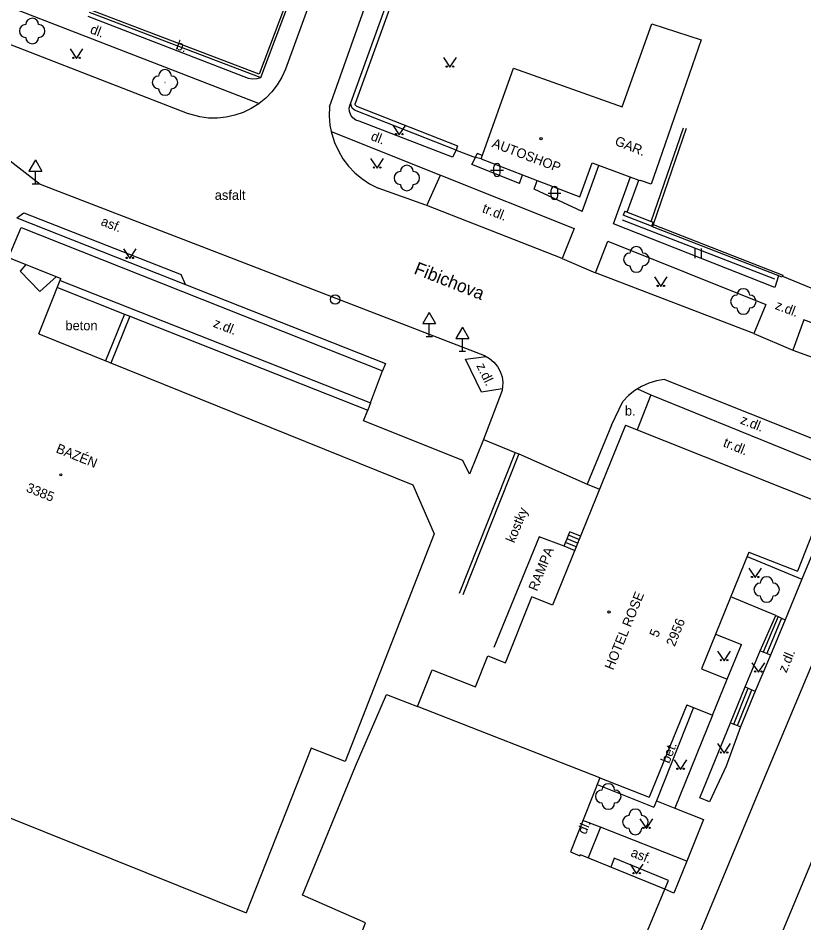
# Model space of a CAD drawing. Extents: x -584400 to -581602, y -1210894 to -1208793.
# Drawn here: x -583343.1 to -583281.7, y -1210558.7 to -1210488 of the extents above; entities that cross this region are included whole.
import ezdxf

# ---------------------------------------------------------------- set-up
doc = ezdxf.new("R2010")
doc.units = 0
for name, color, linetype in [('BUDOVY_MĚŘ', 7, 'Continuous'), ('MAP_ZN_BP', 7, 'Continuous'), ('NÁZVY_ULIC_TOK_SMĚR', 7, 'Continuous'), ('POMOC_POPIS', 7, 'Continuous'), ('ROZHRANÍ_PLOCH', 7, 'Continuous'), ('ZELEŇ', 7, 'Continuous'), ('ZN_BUDOV', 7, 'Continuous'), ('ZN_DOPLŇKOVÉ', 7, 'Continuous'), ('ZN_KULTUR', 7, 'Continuous'), ('Č_POPIS_EVID', 7, 'Continuous')]:
    doc.layers.add(name, color=color, linetype=linetype)

msp = doc.modelspace()

# ---------------------------------------------------------------- linework, layer by layer
at = {"layer": 'BUDOVY_MĚŘ'}
for points in [[(-583306.95, -1210499.01), (-583304.42, -1210491.92), (-583295.92, -1210494.95), (-583293.6, -1210488.45), (-583289.76, -1210489.69), (-583293.04, -1210499.19), (-583293.66, -1210500.99), (-583294.49, -1210500.7)], [(-583306.95, -1210499.01), (-583303.72, -1210500.26)], [(-583302.56, -1210500.7), (-583299.23, -1210501.98), (-583298.26, -1210499.32), (-583294.61, -1210500.66), (-583294.49, -1210500.7)], [(-583358.67, -1210504.38), (-583355.01, -1210502.25), (-583339.78, -1210508.36)], [(-583341.52, -1210512.69), (-583339.78, -1210508.36)], [(-583341.52, -1210512.69), (-583312.28, -1210524.49), (-583310.62, -1210528.33)], [(-583295.67, -1210519.82), (-583301.37, -1210533.9), (-583302.98, -1210533.25)], [(-583295.67, -1210519.82), (-583280.16, -1210526), (-583282.23, -1210531.25)], [(-583310.62, -1210528.33), (-583317.56, -1210546.13), (-583320.24, -1210545.08), (-583325.3, -1210557.96)], [(-583286.02, -1210529.75), (-583289.73, -1210538.88), (-583287.71, -1210539.7)], [(-583286.02, -1210529.75), (-583282.23, -1210531.25)], [(-583311.91, -1210541.83), (-583310.78, -1210538.95), (-583307.38, -1210540.28), (-583306.43, -1210537.86), (-583305.05, -1210538.4), (-583302.98, -1210533.25)], [(-583372.65, -1210538.93), (-583325.3, -1210557.96)], [(-583290.88, -1210541.69), (-583288.85, -1210542.51), (-583287.71, -1210539.7)], [(-583307.97, -1210568.9), (-583318.27, -1210564.75), (-583315.99, -1210558.73), (-583320.9, -1210556.58), (-583316.75, -1210546.49), (-583314.35, -1210540.88), (-583311.91, -1210541.83)], [(-583297.66, -1210547.41), (-583311.91, -1210541.83)], [(-583290.88, -1210541.69), (-583293.82, -1210548.92)], [(-583297.66, -1210547.41), (-583299.97, -1210553.19), (-583299.22, -1210553.49), (-583299.19, -1210553.42)], [(-583297.66, -1210547.41), (-583293.82, -1210548.92)], [(-583294.2, -1210559.98), (-583292.59, -1210556.1), (-583299.19, -1210553.42)]]:
    msp.add_lwpolyline(points, dxfattribs=at)
at = {"layer": 'MAP_ZN_BP'}
for radius in [0.375, 0.0005]:
    msp.add_circle((-583318.35, -1210510.001), radius, dxfattribs=at)
at = {"layer": 'ROZHRANÍ_PLOCH'}
for points in [[(-583313.01, -1210330.05), (-583293.77, -1210336.88), (-583274.64, -1210343.78), (-583274.01, -1210344.01), (-583273.4, -1210344.32), (-583272.84, -1210344.7), (-583272.32, -1210345.14), (-583271.87, -1210345.64), (-583271.47, -1210346.19), (-583271.14, -1210346.78), (-583270.88, -1210347.41), (-583270.7, -1210348.06), (-583270.59, -1210348.73), (-583270.57, -1210349.41), (-583270.62, -1210350.09), (-583270.76, -1210350.75), (-583270.94, -1210351.31), (-583322.23, -1210492)], [(-583318.8, -1210494.94), (-583312.35, -1210476.76)], [(-583356.54, -1210482.16), (-583324.28, -1210494.67)], [(-583324.28, -1210494.67), (-583324.32, -1210494.7), (-583324.91, -1210495.07), (-583325.53, -1210495.37), (-583326.18, -1210495.6), (-583326.86, -1210495.75), (-583327.55, -1210495.82), (-583328.24, -1210495.82), (-583328.93, -1210495.73), (-583329.9, -1210495.46), (-583348.95, -1210488.05)], [(-583337.69, -1210487.86), (-583325.15, -1210492.7), (-583324.8, -1210492.75), (-583324.44, -1210492.72), (-583324.16, -1210492.64)], [(-583322.23, -1210492), (-583322.52, -1210492.63), (-583322.88, -1210493.22), (-583323.3, -1210493.77), (-583323.78, -1210494.27), (-583324.28, -1210494.67)], [(-583350.67, -1210493.78), (-583341.4, -1210500.99), (-583306.67, -1210514.38), (-583306.29, -1210514.61), (-583305.95, -1210514.9), (-583305.67, -1210515.24), (-583305.46, -1210515.64), (-583305.31, -1210516.06), (-583305.25, -1210516.5), (-583305.3, -1210517.12), (-583306.75, -1210520.95)], [(-583318.8, -1210494.94), (-583318.82, -1210495.65), (-583318.76, -1210496.36), (-583318.66, -1210496.87)], [(-583308.9, -1210498.32), (-583309.17, -1210498.87), (-583316.48, -1210496.07), (-583316.74, -1210495.97), (-583316.97, -1210495.8), (-583317.14, -1210495.58), (-583317.23, -1210495.31), (-583317.25, -1210495.03), (-583317.19, -1210494.76), (-583317.13, -1210494.62)], [(-583318.66, -1210496.87), (-583318.61, -1210497.06), (-583318.4, -1210497.74), (-583318.1, -1210498.39), (-583317.74, -1210499.01), (-583317.31, -1210499.57), (-583316.81, -1210500.09), (-583316.27, -1210500.55), (-583315.67, -1210500.95), (-583315, -1210501.29)], [(-583318.66, -1210496.87), (-583310.13, -1210500.29)], [(-583307.67, -1210499.46), (-583307.38, -1210498.91)], [(-583303.94, -1210500.92), (-583307.67, -1210499.46)], [(-583299.04, -1210503.11), (-583297.74, -1210499.52)], [(-583310.13, -1210500.29), (-583299.68, -1210504.46), (-583300.6, -1210506.8), (-583311.18, -1210502.66), (-583310.13, -1210500.29)], [(-583303.94, -1210500.92), (-583303.72, -1210500.26)], [(-583302.79, -1210501.37), (-583302.56, -1210500.7)], [(-583283.7, -1210508.15), (-583283.99, -1210509.07), (-583296.6, -1210504.08), (-583295.27, -1210500.42)], [(-583311.26, -1210502.63), (-583315, -1210501.29)], [(-583299.04, -1210503.11), (-583302.79, -1210501.37)], [(-583343.23, -1210503.61), (-583342.67, -1210503.22), (-583330.38, -1210508.06)], [(-583343.23, -1210503.61), (-583330.05, -1210508.83)], [(-583343.87, -1210506.72), (-583342.9, -1210504.38), (-583314.65, -1210515.58)], [(-583298.01, -1210507.91), (-583297.05, -1210505.45), (-583284.69, -1210510.4), (-583285.63, -1210512.65), (-583298.01, -1210507.91)], [(-583342.52, -1210507.26), (-583342.96, -1210507.78), (-583341.44, -1210509.39), (-583340.13, -1210508.21)], [(-583300.6, -1210506.8), (-583298.01, -1210507.91)], [(-583339.84, -1210508.51), (-583315.6, -1210518.09), (-583315.81, -1210518.65)], [(-583330.05, -1210508.83), (-583330.38, -1210508.06)], [(-583340.06, -1210509.07), (-583334.81, -1210511.14)], [(-583330.05, -1210508.83), (-583314.43, -1210515.02), (-583314.65, -1210515.58)], [(-583334.81, -1210511.14), (-583336.3, -1210514.8)], [(-583334.39, -1210511.31), (-583335.89, -1210514.97)], [(-583334.81, -1210511.14), (-583334.39, -1210511.31)], [(-583334.39, -1210511.31), (-583315.81, -1210518.65)], [(-583272.19, -1210517.74), (-583271.46, -1210515.49), (-583281.72, -1210511.59), (-583282.59, -1210513.96), (-583272.19, -1210517.74)], [(-583285.63, -1210512.65), (-583282.59, -1210513.96)], [(-583305.29, -1210517), (-583306.91, -1210517.26), (-583308.17, -1210514.66), (-583306.54, -1210514.46)], [(-583315.6, -1210518.09), (-583314.65, -1210515.58)], [(-583292.64, -1210516.25), (-583293.25, -1210516.36), (-583293.85, -1210516.54), (-583294.41, -1210516.8), (-583294.94, -1210517.12), (-583295.43, -1210517.52), (-583295.87, -1210517.99)], [(-583271.92, -1210529.55), (-583272.06, -1210528.73), (-583272.28, -1210527.92), (-583272.58, -1210527.13), (-583272.94, -1210526.38), (-583273.37, -1210525.69), (-583274.55, -1210524.17), (-583275.05, -1210523.69), (-583275.59, -1210523.27), (-583276.18, -1210522.91), (-583276.81, -1210522.63), (-583276.98, -1210522.57), (-583279.19, -1210521.64), (-583292.64, -1210516.25)], [(-583294.73, -1210516.98), (-583293.67, -1210517.46), (-583294.74, -1210520.19)], [(-583293.67, -1210517.46), (-583279.82, -1210523.09)], [(-583296.76, -1210519.82), (-583295.87, -1210517.99)], [(-583306.75, -1210520.95), (-583307.86, -1210523.67), (-583308.38, -1210522.59), (-583316.14, -1210519.48), (-583315.81, -1210518.65)], [(-583296.76, -1210519.82), (-583298.65, -1210524.45)], [(-583306.75, -1210520.95), (-583304.28, -1210521.97)], [(-583304, -1210522.08), (-583298.65, -1210524.45)], [(-583280.88, -1210525.72), (-583279.82, -1210523.09), (-583278.92, -1210524.73), (-583281.87, -1210531.86)], [(-583298.65, -1210524.45), (-583297.7, -1210524.83)], [(-583300.23, -1210528.72), (-583300.12, -1210528.44)], [(-583300.12, -1210528.44), (-583300.01, -1210528.17)], [(-583299.3, -1210528.78), (-583300.12, -1210528.44)], [(-583299.18, -1210528.5), (-583300.01, -1210528.17)], [(-583300.46, -1210529.29), (-583302.4, -1210528.55), (-583305.94, -1210537.22)], [(-583300.46, -1210529.29), (-583300.34, -1210529)], [(-583300.34, -1210529), (-583300.23, -1210528.72)], [(-583299.52, -1210529.34), (-583300.34, -1210529)], [(-583299.41, -1210529.06), (-583300.23, -1210528.72)], [(-583299.64, -1210529.63), (-583300.46, -1210529.29)], [(-583286.16, -1210530.11), (-583281.87, -1210531.86)], [(-583281.87, -1210531.86), (-583283.19, -1210535.05)], [(-583283.91, -1210534.71), (-583287.44, -1210533.25)], [(-583285.13, -1210537.48), (-583283.91, -1210534.71)], [(-583283.74, -1210534.79), (-583284.9, -1210537.57)], [(-583283.91, -1210534.71), (-583283.74, -1210534.79)], [(-583283.74, -1210534.79), (-583283.47, -1210534.92)], [(-583283.47, -1210534.92), (-583284.62, -1210537.69)], [(-583283.19, -1210535.05), (-583284.34, -1210537.8)], [(-583283.47, -1210534.92), (-583283.19, -1210535.05)], [(-583288.63, -1210536.17), (-583286.6, -1210536.99)], [(-583287.71, -1210539.7), (-583286.6, -1210536.99)], [(-583294.34, -1210570.37), (-583284.9, -1210547.66), (-583280.49, -1210537.15)], [(-583286.32, -1210540.3), (-583285.13, -1210537.48)], [(-583284.9, -1210537.57), (-583285.13, -1210537.48)], [(-583284.62, -1210537.69), (-583284.9, -1210537.57)], [(-583284.34, -1210537.8), (-583284.62, -1210537.69)], [(-583284.34, -1210537.8), (-583285.52, -1210540.63)], [(-583311.81, -1210627.97), (-583302.23, -1210604.91), (-583291.71, -1210579.41), (-583279.57, -1210550.25), (-583275.08, -1210539.62)], [(-583287.46, -1210543.1), (-583286.32, -1210540.3)], [(-583287.2, -1210543.2), (-583286.07, -1210540.4)], [(-583286.92, -1210543.31), (-583285.8, -1210540.51)], [(-583286.32, -1210540.3), (-583286.07, -1210540.4)], [(-583286.07, -1210540.4), (-583285.8, -1210540.51)], [(-583285.8, -1210540.51), (-583285.52, -1210540.63)], [(-583285.52, -1210540.63), (-583286.68, -1210543.41)], [(-583290.34, -1210541.91), (-583293.25, -1210549.21)], [(-583288.85, -1210542.51), (-583291.81, -1210549.77)], [(-583286.68, -1210543.41), (-583287.8, -1210546.5), (-583289.09, -1210549.28), (-583289.84, -1210548.96), (-583287.46, -1210543.1)], [(-583287.46, -1210543.1), (-583287.2, -1210543.2)], [(-583287.2, -1210543.2), (-583286.92, -1210543.31)], [(-583286.92, -1210543.31), (-583286.68, -1210543.41)], [(-583297.87, -1210547.93), (-583293.45, -1210549.7)], [(-583293.25, -1210549.21), (-583293.45, -1210549.7)], [(-583293.25, -1210549.21), (-583291.81, -1210549.77)], [(-583291.81, -1210549.77), (-583289.57, -1210550.65), (-583290.87, -1210553.92)], [(-583297.61, -1210551.27), (-583298.99, -1210550.73)], [(-583297.61, -1210551.27), (-583298.58, -1210553.67)], [(-583290.87, -1210553.92), (-583297.61, -1210551.27)], [(-583290.87, -1210553.92), (-583291.89, -1210556.43), (-583292.59, -1210556.1), (-583292.31, -1210555.44), (-583296.54, -1210553.69), (-583296.81, -1210554.39)], [(-583290.85, -1210553.93), (-583290.87, -1210553.92)]]:
    msp.add_lwpolyline(points, dxfattribs=at)
at = {"layer": 'ZELEŇ'}
for centre in [(-583342.03, -1210489.01), (-583331.65, -1210493.03), (-583312.75, -1210500.5), (-583294.81, -1210506.87), (-583286.45, -1210510.16), (-583284.63, -1210532.68), (-583297.01, -1210548.86), (-583294.89, -1210550.85)]:
    msp.add_circle(centre, 0.0005, dxfattribs=at)
for centre, start, end in [((-583342.03, -1210488.51), 0, 179.99999), ((-583342.53, -1210489.01), 89.99999, 269.99999), ((-583341.53, -1210489.01), 270, 89.99999), ((-583342.03, -1210489.51), 179.99999, 359.99999), ((-583331.65, -1210492.53), 0, 179.99999), ((-583332.15, -1210493.03), 89.99999, 269.99999), ((-583331.15, -1210493.03), 270, 89.99999), ((-583331.65, -1210493.53), 179.99999, 359.99999), ((-583312.75, -1210500), 0, 179.99999), ((-583313.25, -1210500.5), 89.99999, 269.99999), ((-583312.25, -1210500.5), 270, 89.99999), ((-583312.75, -1210501), 179.99999, 359.99999), ((-583294.81, -1210506.37), 0, 179.99999), ((-583295.31, -1210506.87), 89.99999, 269.99999), ((-583294.31, -1210506.87), 270, 89.99999), ((-583294.81, -1210507.37), 179.99999, 359.99999), ((-583286.45, -1210509.66), 0, 179.99999), ((-583286.95, -1210510.16), 89.99999, 269.99999), ((-583285.95, -1210510.16), 270, 89.99999), ((-583286.45, -1210510.66), 179.99999, 359.99999), ((-583284.63, -1210532.18), 0, 179.99999), ((-583285.13, -1210532.68), 89.99999, 269.99999), ((-583284.13, -1210532.68), 270, 89.99999), ((-583284.63, -1210533.18), 179.99999, 359.99999), ((-583297.01, -1210548.36), 0, 179.99999), ((-583297.51, -1210548.86), 89.99999, 269.99999), ((-583296.51, -1210548.86), 270, 89.99999), ((-583297.01, -1210549.36), 179.99999, 359.99999), ((-583295.39, -1210550.85), 89.99999, 269.99999), ((-583294.89, -1210550.35), 0, 179.99999), ((-583294.39, -1210550.85), 270, 89.99999), ((-583294.89, -1210551.35), 179.99999, 359.99999)]:
    msp.add_arc(centre, 0.5, start, end, dxfattribs=at)
at = {"layer": 'ZN_BUDOV'}
for centre in [(-583302.26, -1210497.42), (-583339.79, -1210523.71), (-583296.95, -1210534.43)]:
    msp.add_circle(centre, 0.0875, dxfattribs=at)
at = {"layer": 'ZN_DOPLŇKOVÉ'}
for p, q in [((-583341.78, -1210499.094), (-583342.28, -1210499.96)), ((-583341.78, -1210499.094), (-583341.28, -1210499.96)), ((-583342.28, -1210499.96), (-583341.28, -1210499.96)), ((-583341.78, -1210500.96), (-583341.78, -1210499.96)), ((-583342.03, -1210500.96), (-583341.53, -1210500.96)), ((-583311, -1210511.024), (-583311.5, -1210511.89)), ((-583311, -1210511.024), (-583310.5, -1210511.89)), ((-583311.5, -1210511.89), (-583310.5, -1210511.89)), ((-583311, -1210512.89), (-583311, -1210511.89)), ((-583308.41, -1210512.174), (-583308.91, -1210513.04)), ((-583308.41, -1210512.174), (-583307.91, -1210513.04)), ((-583311.25, -1210512.89), (-583310.75, -1210512.89)), ((-583308.91, -1210513.04), (-583307.91, -1210513.04)), ((-583308.41, -1210514.04), (-583308.41, -1210513.04)), ((-583308.66, -1210514.04), (-583308.16, -1210514.04))]:
    msp.add_line(p, q, dxfattribs=at)
for points in [[(-583308.78, -1210498), (-583308.9, -1210498.32), (-583316.85, -1210495.19), (-583317.01, -1210495.04), (-583317.11, -1210494.84), (-583317.13, -1210494.62), (-583310.92, -1210477.46), (-583310.56, -1210477.47)], [(-583310.56, -1210477.47), (-583316.79, -1210494.69)], [(-583337.57, -1210487.53), (-583324.16, -1210492.64), (-583318.68, -1210478.09)], [(-583318.86, -1210478.02), (-583324.28, -1210492.38), (-583337.5, -1210487.35)], [(-583316.69, -1210494.88), (-583316.78, -1210494.77), (-583316.79, -1210494.69)], [(-583316.69, -1210494.88), (-583308.78, -1210498)], [(-583293.65, -1210503.91), (-583291.13, -1210496.57)], [(-583290.92, -1210496.64), (-583293.5, -1210504.14)], [(-583308.9, -1210498.32), (-583307.38, -1210498.91)], [(-583307.38, -1210498.91), (-583307.26, -1210498.59)], [(-583306.85, -1210498.75), (-583307.26, -1210498.59)], [(-583306.95, -1210499.01), (-583307.38, -1210498.91)], [(-583303.72, -1210500.26), (-583302.56, -1210500.7)], [(-583295.53, -1210503.17), (-583294.61, -1210500.66)], [(-583295.72, -1210503.1), (-583295.84, -1210503.41)], [(-583293.64, -1210504.28), (-583295.84, -1210503.41)], [(-583295.72, -1210503.1), (-583293.65, -1210503.91)], [(-583283.98, -1210508.41), (-583295.9, -1210503.8)], [(-583293.65, -1210503.91), (-583293.51, -1210503.96)], [(-583293.51, -1210503.96), (-583293.64, -1210504.28)], [(-583293.56, -1210504.31), (-583293.64, -1210504.28)], [(-583293.5, -1210504.14), (-583293.56, -1210504.31)], [(-583283.36, -1210508.09), (-583283.42, -1210508.26), (-583293.56, -1210504.31)], [(-583293.5, -1210504.14), (-583283.36, -1210508.09)], [(-583283.39, -1210508.17), (-583281.18, -1210509.09)], [(-583304.28, -1210521.97), (-583308.66, -1210532.98)], [(-583304.28, -1210521.97), (-583304, -1210522.08), (-583308.38, -1210533.09)]]:
    msp.add_lwpolyline(points, dxfattribs=at)
at = {"layer": 'ZN_KULTUR'}
for p, q in [((-583306.2, -1210499.88), (-583305.2, -1210499.88)), ((-583305.95, -1210500.13), (-583305.95, -1210499.63)), ((-583305.45, -1210500.13), (-583305.45, -1210499.63)), ((-583301.46, -1210501.93), (-583301.46, -1210501.43)), ((-583300.96, -1210501.93), (-583300.96, -1210501.43)), ((-583301.71, -1210501.68), (-583300.71, -1210501.68)), ((-583290.21, -1210506.765), (-583290.21, -1210506.015)), ((-583289.71, -1210506.765), (-583289.71, -1210506.015))]:
    msp.add_line(p, q, dxfattribs=at)
for points in [[(-583339.06, -1210490.41), (-583338.56, -1210491.16), (-583338.06, -1210490.41)], [(-583309.88, -1210491.09), (-583309.38, -1210491.84), (-583308.88, -1210491.09)], [(-583313.84, -1210496.37), (-583313.34, -1210497.12), (-583312.84, -1210496.37)], [(-583315.58, -1210498.98), (-583315.08, -1210499.73), (-583314.58, -1210498.98)], [(-583334.9, -1210506.05), (-583334.4, -1210506.8), (-583333.9, -1210506.05)], [(-583293.4, -1210508.24), (-583292.9, -1210508.99), (-583292.4, -1210508.24)], [(-583286.03, -1210531), (-583285.53, -1210531.75), (-583285.03, -1210531)], [(-583288.46, -1210537.5), (-583287.96, -1210538.25), (-583287.46, -1210537.5)], [(-583285.78, -1210538.4), (-583285.28, -1210539.15), (-583284.78, -1210538.4)], [(-583288.46, -1210544.72), (-583287.96, -1210545.47), (-583287.46, -1210544.72)], [(-583291.86, -1210545.99), (-583291.36, -1210546.74), (-583290.86, -1210545.99)], [(-583294.53, -1210550.61), (-583294.03, -1210551.36), (-583293.53, -1210550.61)], [(-583295.29, -1210554.15), (-583294.79, -1210554.9), (-583294.29, -1210554.15)]]:
    msp.add_lwpolyline(points, dxfattribs=at)
for centre in [(-583338.81, -1210491.11), (-583338.31, -1210491.11), (-583309.63, -1210491.79), (-583309.13, -1210491.79), (-583313.59, -1210497.07), (-583313.09, -1210497.07), (-583315.33, -1210499.68), (-583314.83, -1210499.68), (-583334.65, -1210506.75), (-583334.15, -1210506.75), (-583293.15, -1210508.94), (-583292.65, -1210508.94), (-583285.78, -1210531.7), (-583285.28, -1210531.7), (-583288.21, -1210538.2), (-583287.71, -1210538.2), (-583285.53, -1210539.1), (-583285.03, -1210539.1), (-583288.21, -1210545.42), (-583287.71, -1210545.42), (-583291.61, -1210546.69), (-583291.11, -1210546.69), (-583294.28, -1210551.31), (-583293.78, -1210551.31), (-583295.04, -1210554.85), (-583294.54, -1210554.85)]:
    msp.add_circle(centre, 0.05, dxfattribs=at)
for centre, start, end in [((-583305.7, -1210499.63), 0, 179.99999), ((-583305.7, -1210500.13), 179.99999, 359.99999), ((-583301.21, -1210501.43), 0, 179.99999), ((-583301.21, -1210501.93), 179.99999, 359.99999)]:
    msp.add_arc(centre, 0.25, start, end, dxfattribs=at)

# ---------------------------------------------------------------- texts
at = {"layer": 'NÁZVY_ULIC_TOK_SMĚR'}
msp.add_text('Fibichova', height=1, rotation=338.457, dxfattribs=at).set_placement((-583312.26, -1210507.96))
at = {"layer": 'POMOC_POPIS'}
for s, rotation, p in [('dl.', 338.80438, (-583337.56, -1210489.16)), ('b.', 338.89514, (-583330.86, -1210490.4)), ('dl.', 338.96246, (-583315.62, -1210497.52)), ('GAR.', 338.11299, (-583296.56, -1210497.89)), ('AUTOSHOP', 339.22774, (-583306.16, -1210498.07)), ('tr.dl.', 338.62361, (-583306.92, -1210503.16)), ('asf.', 338.50553, (-583336.72, -1210504.17)), ('z.dl.', 339.18735, (-583284.03, -1210510.73)), ('z.dl.', 338.43534, (-583327.94, -1210512.12)), ('z.dl.', 295.85552, (-583307.33, -1210515.18)), (' z.dl.', 338.25211, (-583287.01, -1210519.58)), ('BAZÉN', 338.02315, (-583340.23, -1210521.94)), ('tr.dl.', 337.87837, (-583288.09, -1210521.47)), ('kostky', 67.78956, (-583304.35, -1210529.09)), ('RAMPA', 67.96122, (-583302.58, -1210532.86)), (' HOTEL ROSE', 67.85957, (-583296.73, -1210539.29)), ('z.dl.', 67.23706, (-583283.09, -1210539.24)), ('bet.', 68.26626, (-583292.25, -1210546.33)), ('dl.', 67.44584, (-583298.76, -1210551.88)), ('asf.', 338.49911, (-583295.31, -1210553.52))]:
    msp.add_text(s, height=0.75, rotation=rotation, dxfattribs=at).set_placement(p)
for s, p in [('asfalt', (-583327.76, -1210502.21)), ('beton', (-583339.43, -1210512.41)), ('b.', (-583295.71, -1210519.08))]:
    msp.add_text(s, height=0.75, dxfattribs=at).set_placement(p)
at = {"layer": 'Č_POPIS_EVID'}
for s, rotation, p in [('3385', 338.02315, (-583342.56, -1210525)), ('2956', 68.01158, (-583291.82, -1210537.19)), ('5', 68.01158, (-583293.13, -1210536.48))]:
    msp.add_text(s, height=0.75, rotation=rotation, dxfattribs=at).set_placement(p)

doc.saveas('drawing.dxf')
